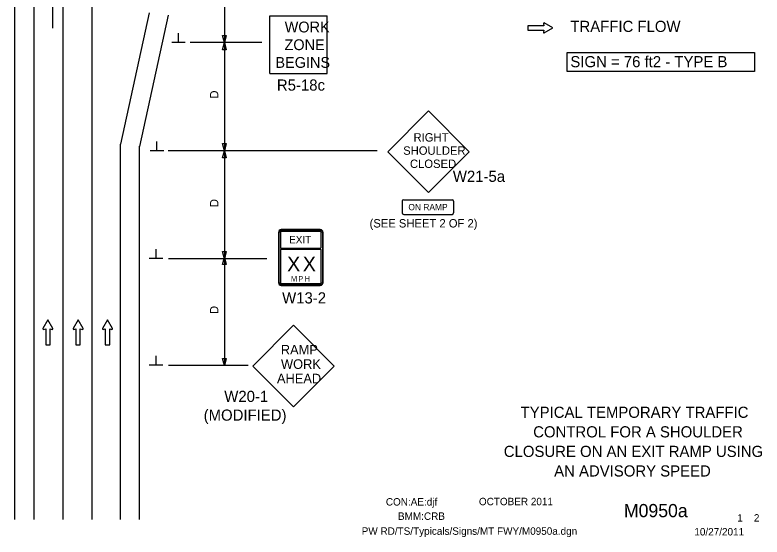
# Model space of a CAD drawing. Extents: x 16480 to 18471, y 4908 to 7082.
# Drawn here: x 16781 to 17404, y 6006 to 6441 of the extents above; entities that cross this region are included whole.
import ezdxf

# ---------------------------------------------------------------- set-up
doc = ezdxf.new("R2010")
doc.units = 0
for name, color, linetype in [('ALI_LEGAL_EX', 7, 'Continuous'), ('BORDER', 7, 'Continuous'), ('BORDER_SIGNAL_WO', 7, 'Continuous'), ('MT_SCRATCH_LEVEL_B', 7, 'Continuous'), ('MT_SCRATCH_LEVEL_E', 7, 'Continuous'), ('PAVT_EDGE_EX', 7, 'Continuous'), ('TRAFFIC_SIGNS_PR', 7, 'Continuous'), ('TYPICAL_TEXT_DIMEN_EX', 7, 'Continuous'), ('TYPICAL_TEXT_DIMEN_PR', 7, 'Continuous')]:
    doc.layers.add(name, color=color, linetype=linetype)

msp = doc.modelspace()

# ---------------------------------------------------------------- linework, layer by layer
at = {"layer": 'ALI_LEGAL_EX'}
for p, q in [((16813.1, 6429.87), (16813.1, 7082.19)), ((16821.4, 6975.1), (16821.4, 6020.66)), ((16845.4, 6975.1), (16845.4, 6020.66))]:
    msp.add_line(p, q, dxfattribs=at)
for points in [[(16821.4, 6375.1), (16821.4, 6350.1)], [(16845.4, 6375.1), (16845.4, 6350.1)], [(16821.4, 6275.1), (16821.4, 6250.1)], [(16845.4, 6275.1), (16845.4, 6250.1)], [(16821.4, 6175.1), (16821.4, 6150.1)], [(16845.4, 6175.1), (16845.4, 6150.1)], [(16821.4, 6075.1), (16821.4, 6050.1)], [(16845.4, 6075.1), (16845.4, 6050.1)]]:
    msp.add_lwpolyline(points, dxfattribs=at)
at = {"layer": 'MT_SCRATCH_LEVEL_E'}
for p, q in [((17222.35, 6432.01), (17209.09, 6432.01)), ((17209.09, 6432.01), (17209.09, 6428.27)), ((17222.35, 6432.01), (17209.09, 6432.01)), ((17209.09, 6432.01), (17209.09, 6428.27)), ((17222.04, 6433.79), (17222.35, 6432.01)), ((17222.04, 6433.79), (17222.35, 6432.01)), ((17229.96, 6430.16), (17222.72, 6434.27)), ((17229.96, 6430.16), (17222.72, 6434.27)), ((17222.72, 6426.01), (17229.96, 6430.16)), ((17222.72, 6426.01), (17229.96, 6430.16)), ((17209.09, 6428.27), (17222.35, 6428.27)), ((17209.09, 6428.27), (17222.35, 6428.27)), ((17222.35, 6428.27), (17222.04, 6426.49)), ((17222.35, 6428.27), (17222.04, 6426.49)), ((16808.89, 6186.92), (16804.78, 6179.68)), ((16813.04, 6179.68), (16808.89, 6186.92)), ((16834.03, 6186.92), (16829.92, 6179.68)), ((16838.18, 6179.68), (16834.03, 6186.92)), ((16858.55, 6186.92), (16854.44, 6179.68)), ((16862.7, 6179.68), (16858.55, 6186.92)), ((16805.26, 6179), (16807.04, 6179.31)), ((16807.04, 6179.31), (16807.04, 6166.06)), ((16810.78, 6166.06), (16810.78, 6179.31)), ((16810.78, 6179.31), (16812.56, 6179)), ((16830.41, 6179), (16832.18, 6179.31)), ((16832.18, 6179.31), (16832.18, 6166.06)), ((16835.92, 6166.06), (16835.92, 6179.31)), ((16835.92, 6179.31), (16837.7, 6179)), ((16854.92, 6179), (16856.7, 6179.31)), ((16856.7, 6179.31), (16856.7, 6166.06)), ((16860.44, 6166.06), (16860.44, 6179.31)), ((16860.44, 6179.31), (16862.22, 6179)), ((16807.04, 6166.06), (16810.78, 6166.06)), ((16832.18, 6166.06), (16835.92, 6166.06)), ((16856.7, 6166.06), (16860.44, 6166.06))]:
    msp.add_line(p, q, dxfattribs=at)
for centre, start, end in [((17222.5, 6433.86), 60.42484, 189.96381), ((17222.5, 6433.86), 60.42484, 189.96381), ((17222.5, 6426.42), 170.03619, 299.77312), ((17222.5, 6426.42), 170.03619, 299.77312), ((16805.19, 6179.46), 150.42484, 279.96381), ((16812.63, 6179.46), 260.03619, 29.77312), ((16830.33, 6179.46), 150.42484, 279.96381), ((16837.77, 6179.46), 260.03619, 29.77312), ((16854.85, 6179.46), 150.42484, 279.96381), ((16862.29, 6179.46), 260.03619, 29.77312)]:
    msp.add_arc(centre, 0.463, start, end, dxfattribs=at)
at = {"layer": 'PAVT_EDGE_EX'}
for p, q in [((16781.4, 6020.66), (16781.4, 6865.57)), ((16797.4, 6020.66), (16797.4, 6865.57)), ((16893.33, 6442.69), (16869.4, 6333.19)), ((16909.24, 6440.87), (16885.31, 6331.37)), ((16869.4, 6020.66), (16869.4, 6333.19)), ((16885.31, 6020.66), (16885.31, 6331.57))]:
    msp.add_line(p, q, dxfattribs=at)
at = {"layer": 'TRAFFIC_SIGNS_PR'}
for p, q in [((16993.83, 6392.2), (16993.83, 6440.2)), ((16993.83, 6440.2), (17041.83, 6440.2)), ((17041.83, 6392.2), (17041.83, 6440.2)), ((16993.83, 6392.2), (17041.83, 6392.2)), ((17126.3, 6360.96), (17092.36, 6327.02)), ((17160.24, 6327.02), (17126.3, 6360.96)), ((17092.36, 6327.02), (17126.3, 6293.08)), ((17126.3, 6293.08), (17160.24, 6327.02)), ((17105.57, 6287.01), (17145.95, 6287.01)), ((17104.32, 6285.76), (17104.32, 6276.01)), ((17147.2, 6285.76), (17147.2, 6276.01)), ((17105.57, 6274.76), (17145.95, 6274.76)), ((17036.02, 6262.12), (17003.5, 6262.12)), ((17001.18, 6259.8), (17001.18, 6217.99)), ((17038.34, 6217.99), (17038.34, 6259.8)), ((17003.5, 6215.67), (17036.02, 6215.67)), ((17013.64, 6182.4), (16979.7, 6148.45)), ((17047.58, 6148.45), (17013.64, 6182.4)), ((16979.7, 6148.45), (17013.64, 6114.51)), ((17013.64, 6114.51), (17047.58, 6148.45))]:
    msp.add_line(p, q, dxfattribs=at)
for points in [[(17036.02, 6262.12), (17003.5, 6262.12)], [(17003.5, 6261.54), (17036.02, 6261.54)], [(17001.18, 6259.8), (17001.18, 6217.99)], [(17001.76, 6217.99), (17001.76, 6259.8)], [(17002.73, 6259.8), (17002.73, 6247.41)], [(17036.02, 6260.58), (17003.5, 6260.58)], [(17036.79, 6247.41), (17036.79, 6259.8)], [(17037.76, 6259.8), (17037.76, 6217.99)], [(17038.34, 6217.99), (17038.34, 6259.8)], [(17002.73, 6244.9), (17002.73, 6217.99)], [(17003.5, 6246.64), (17036.02, 6246.64)], [(17036.02, 6245.67), (17003.5, 6245.67)], [(17036.79, 6217.99), (17036.79, 6244.9)], [(17003.5, 6217.22), (17036.02, 6217.22)], [(17036.02, 6216.25), (17003.5, 6216.25)], [(17003.5, 6215.67), (17036.02, 6215.67)]]:
    msp.add_lwpolyline(points, dxfattribs=at)
for centre, radius, start, end in [((17105.57, 6285.76), 1.25, 90, 180), ((17145.95, 6285.76), 1.25, 0, 90), ((17105.57, 6276.01), 1.25, 180, 270), ((17145.95, 6276.01), 1.25, 270, 0), ((17003.5, 6259.8), 2.32, 90.00021, 179.99985), ((17003.5, 6259.8), 2.32, 90.00021, 179.99985), ((17003.5, 6259.8), 1.74, 90.00021, 179.99985), ((17036.02, 6259.8), 2.32, 0, 90.00021), ((17036.02, 6259.8), 2.32, 0, 90.00021), ((17036.02, 6259.8), 1.74, 360, 90.00021), ((17003.5, 6259.8), 0.774, 90.00021, 179.99985), ((17036.02, 6259.8), 0.774, 0, 90.00021), ((17003.5, 6247.41), 0.774, 179.99985, 270.00006), ((17003.5, 6244.9), 0.774, 90.00021, 179.99985), ((17036.02, 6247.41), 0.774, 270.00006, 0.00027), ((17036.02, 6244.9), 0.774, 0, 90.00021), ((17003.5, 6217.99), 2.32, 179.99985, 270.00006), ((17003.5, 6217.99), 2.32, 179.99985, 270.00006), ((17003.5, 6217.99), 1.74, 179.99985, 270.00006), ((17003.5, 6217.99), 0.774, 179.99985, 270.00006), ((17036.02, 6217.99), 2.32, 270.00006, 0.00027), ((17036.02, 6217.99), 2.32, 270.00006, 0.00027), ((17036.02, 6217.99), 1.74, 270.00006, 0.00027), ((17036.02, 6217.99), 0.774, 270.00006, 0.00027)]:
    msp.add_arc(centre, radius, start, end, dxfattribs=at)
at = {"layer": 'TYPICAL_TEXT_DIMEN_PR'}
for p, q in [((16956.04, 6507.88), (16956.04, 6417.88)), ((16917.76, 6417.92), (16917.76, 6425.71)), ((16956.04, 6417.88), (16954.47, 6423.74)), ((16954.47, 6423.74), (16956.04, 6423.74)), ((16956.04, 6423.74), (16957.61, 6423.74)), ((16957.61, 6423.74), (16956.04, 6417.88)), ((16917.76, 6417.92), (16912.14, 6417.92)), ((16923.39, 6417.92), (16917.76, 6417.92)), ((16987.22, 6417.88), (16927.6, 6417.88)), ((16954.47, 6412.02), (16956.04, 6417.88)), ((16956.04, 6417.88), (16956.04, 6327.88)), ((16956.04, 6417.88), (16957.61, 6412.02)), ((16956.04, 6412.02), (16954.47, 6412.02)), ((16957.61, 6412.02), (16956.04, 6412.02)), ((16899.82, 6327.8), (16899.82, 6335.58)), ((16956.04, 6327.88), (16954.47, 6333.74)), ((16954.47, 6333.74), (16956.04, 6333.74)), ((16956.04, 6333.74), (16957.61, 6333.74)), ((16957.61, 6333.74), (16956.04, 6327.88)), ((16899.82, 6327.8), (16894.19, 6327.8)), ((16905.44, 6327.8), (16899.82, 6327.8)), ((17083.37, 6327.88), (16909.05, 6327.88)), ((16954.47, 6322.02), (16956.04, 6327.88)), ((16956.04, 6327.88), (16957.61, 6322.02)), ((16956.04, 6326.92), (16956.04, 6237.88)), ((16956.04, 6322.02), (16954.47, 6322.02)), ((16957.61, 6322.02), (16956.04, 6322.02)), ((16899.07, 6238.08), (16899.07, 6245.87)), ((16956.04, 6237.88), (16954.47, 6243.74)), ((16954.47, 6243.74), (16956.04, 6243.74)), ((16956.04, 6243.74), (16957.61, 6243.74)), ((16957.61, 6243.74), (16956.04, 6237.88)), ((16899.07, 6238.08), (16893.44, 6238.08)), ((16904.69, 6238.08), (16899.07, 6238.08)), ((16991.5, 6237.88), (16909.43, 6237.88)), ((16954.47, 6232.99), (16956.04, 6238.85)), ((16956.04, 6238.85), (16957.61, 6232.99)), ((16956.04, 6237.88), (16956.04, 6148.85)), ((16956.04, 6232.99), (16954.47, 6232.99)), ((16957.61, 6232.99), (16956.04, 6232.99)), ((16899.07, 6149.05), (16899.07, 6156.83)), ((16899.07, 6149.05), (16893.44, 6149.05)), ((16904.69, 6149.05), (16899.07, 6149.05)), ((16956.04, 6148.85), (16954.47, 6154.71)), ((16954.47, 6154.71), (16956.04, 6154.71)), ((16956.04, 6154.71), (16957.61, 6154.71)), ((16957.61, 6154.71), (16956.04, 6148.85)), ((16975.77, 6148.85), (16909.43, 6148.85))]:
    msp.add_line(p, q, dxfattribs=at)
msp.add_lwpolyline([(17241.79, 6409.7), (17397.97, 6409.7), (17397.97, 6393.9), (17241.79, 6393.9)], close=True, dxfattribs=at)

# ---------------------------------------------------------------- texts
at = {"layer": 'BORDER'}
for s, p in [('TYPICAL TEMPORARY TRAFFIC', (17203.04, 6105.28)), ('CONTROL FOR A SHOULDER', (17213.54, 6088.98)), ('CLOSURE ON AN EXIT RAMP USING', (17189.03, 6072.69)), ('AN ADVISORY SPEED', (17231.02, 6056.39))]:
    msp.add_text(s, height=9.3, dxfattribs=at).set_placement(p)
at = {"layer": 'BORDER_SIGNAL_WO'}
for s, height, p in [('CON:AE:djf  ', 6.2, (17090.69, 6032.18)), ('    OCTOBER 2011    ', 6.2, (17159.08, 6032.46)), ('    M0950a   ', 11, (17272.86, 6022.5)), ('BMM:CRB   ', 6.2, (17100.81, 6020.29)), (' 1    2 ', 6.2, (17381.45, 6018.82)), ('PW RD/TS/Typicals/Signs/MT FWY/M0950a.dgn      ', 6.2, (17070.55, 6007.83)), ('10/27/2011    ', 6.2, (17347.93, 6007.25))]:
    msp.add_text(s, height=height, dxfattribs=at).set_placement(p)
at = {"layer": 'MT_SCRATCH_LEVEL_B'}
msp.add_text('(SEE SHEET 2 OF 2)', height=7, dxfattribs=at).set_placement((17077.1, 6263.88))
at = {"layer": 'TRAFFIC_SIGNS_PR'}
for s, height, p in [('WORK', 9.021, (17006.33, 6426.41)), ('ZONE', 9.021, (17006.18, 6411.65)), ('BEGINS', 9.021, (16998.59, 6396.89)), ('R5-18c', 9.3, (16999.84, 6377.9)), ('RIGHT', 7, (17113.77, 6335.47)), ('SHOULDER', 7, (17105.15, 6324.47)), ('CLOSED', 7, (17110.8, 6313.47)), ('W21-5a', 9.3, (17146.56, 6301.89)), ('ON RAMP', 5.25, (17109.46, 6278.26)), ('EXIT', 6.194, (17010.05, 6250.64)), ('X', 12.39, (17008.3, 6227.29)), ('X', 12.39, (17021.36, 6227.29)), ('M', 4.65, (17011.53, 6218.77)), ('P', 4.65, (17017.65, 6218.77)), ('H', 4.65, (17023.01, 6218.77)), ('W13-2', 9.3, (17004.2, 6200.57)), ('RAMP', 8, (17003.09, 6158.06)), ('WORK', 8, (17003.25, 6146.06)), ('AHEAD', 8, (16999.89, 6134.06)), ('W20-1', 9.3, (16955.96, 6118.51)), ('(MODIFIED)', 9.3, (16938.76, 6102.91))]:
    msp.add_text(s, height=height, dxfattribs=at).set_placement(p)
at = {"layer": 'TYPICAL_TEXT_DIMEN_EX'}
msp.add_text('TRAFFIC FLOW', height=9.3, dxfattribs=at).set_placement((17244.54, 6426.8))
at = {"layer": 'TYPICAL_TEXT_DIMEN_PR'}
msp.add_text('SIGN = 76 ft2 - TYPE B', height=9.3, dxfattribs=at).set_placement((17244.54, 6397.4))
for p in [(16951.04, 6371.25), (16951.04, 6280.82), (16951.04, 6191.79)]:
    msp.add_text('D', height=7, rotation=90, dxfattribs=at).set_placement(p)

doc.saveas('drawing.dxf')
